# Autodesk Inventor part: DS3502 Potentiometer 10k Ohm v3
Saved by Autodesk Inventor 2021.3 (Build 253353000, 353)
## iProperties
Created: 2023-09
Part Number: DS3502 Potentiometer 10k Ohm v3
Material: Generic
Document SubType Name: Modeling
Designer: AdminForWorker
Density: 1 g/cm^3
Appearance: Default
Title: DS3502 Potentiometer 10k Ohm v3
Author: AdminForWorker
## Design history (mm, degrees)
feature "Body1"
feature "Body2"
feature "Body3"
feature "Body4"
feature "Body5"
feature "Body6"
feature "Body7"
feature "Body8"
feature "Body9"
feature "Body10"
feature "Body11"
body "Solid1"
body "Solid2"
body "Solid3"
body "Solid4"
body "Solid5"
body "Solid6"
body "Solid7"
body "Solid8"
body "Solid9"
body "Solid10"
body "Solid11"
